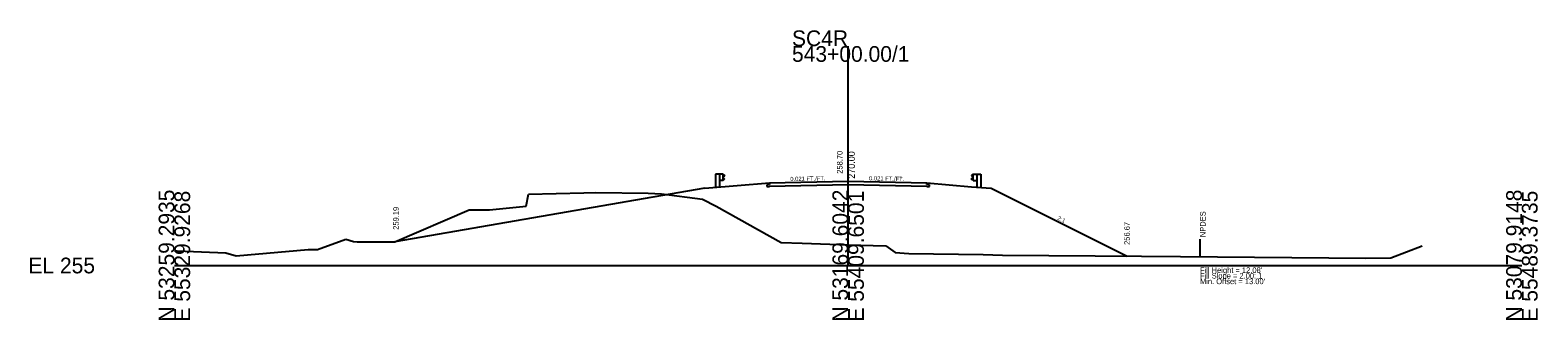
# Model space of a CAD drawing. Extents: x 9740 to 17409, y 8856 to 28416.
# Drawn here: x 11740.2 to 12008.7, y 23861.7 to 23913.3 of the extents above; entities that cross this region are included whole.
import ezdxf

# ---------------------------------------------------------------- set-up
doc = ezdxf.new("R2010")
doc.units = 0
for name, color, linetype in [('Level 10', 7, 'Continuous'), ('Level 11', 7, 'Continuous'), ('Level 12', 7, 'Continuous'), ('Level 24', 7, 'Continuous'), ('Level 32', 7, 'Continuous'), ('Level 33', 7, 'Continuous'), ('Level 50', 7, 'Continuous'), ('Level 55', 7, 'Continuous'), ('Level 59', 7, 'Continuous'), ('Level 6', 7, 'Continuous'), ('Level 60', 7, 'Continuous'), ('Level 63', 7, 'Continuous'), ('Level 7', 7, 'Continuous')]:
    doc.layers.add(name, color=color, linetype=linetype)

msp = doc.modelspace()

# ---------------------------------------------------------------- linework, layer by layer
at = {"layer": 'Level 11'}
for p, q in [((11871.85, 23885.79), (11871.35, 23885.78)), ((11871.35, 23885.78), (11871.35, 23885.44)), ((11871.35, 23885.44), (11871.85, 23885.45)), ((11871.85, 23886.09), (11871.85, 23885.79)), ((11899.85, 23885.79), (11899.85, 23886.09)), ((11900.35, 23885.78), (11899.85, 23885.79)), ((11899.85, 23885.45), (11900.35, 23885.44)), ((11900.35, 23885.44), (11900.35, 23885.78))]:
    msp.add_line(p, q, dxfattribs=at)
at = {"layer": 'Level 12'}
for p, q in [((11885.85, 23885.74), (11871.85, 23885.45)), ((11899.85, 23885.45), (11885.85, 23885.74))]:
    msp.add_line(p, q, dxfattribs=at)
at = {"layer": 'Level 24'}
for p, q in [((11862.92, 23887.67), (11862.25, 23887.67)), ((11862.25, 23887.67), (11862.25, 23885.29)), ((11863.58, 23887.67), (11862.92, 23887.67)), ((11862.92, 23887.67), (11862.92, 23885.34)), ((11863.58, 23886.51), (11862.92, 23886.51)), ((11863.58, 23886.51), (11863.58, 23887.67)), ((11863.58, 23887.6), (11863.85, 23887.4)), ((11863.85, 23887.35), (11863.58, 23887.15)), ((11863.85, 23886.83), (11863.58, 23887.03)), ((11863.58, 23886.58), (11863.85, 23886.78)), ((11863.85, 23887.4), (11863.85, 23887.35)), ((11863.85, 23886.78), (11863.85, 23886.83)), ((11908.12, 23887.6), (11907.85, 23887.4)), ((11907.85, 23887.4), (11907.85, 23887.35)), ((11907.85, 23887.35), (11908.12, 23887.15)), ((11907.85, 23886.83), (11908.12, 23887.03)), ((11907.85, 23886.78), (11907.85, 23886.83)), ((11908.12, 23886.58), (11907.85, 23886.78)), ((11908.12, 23886.51), (11908.12, 23887.67)), ((11908.12, 23887.67), (11908.79, 23887.67)), ((11908.12, 23886.51), (11908.79, 23886.51)), ((11908.79, 23887.67), (11908.79, 23885.34)), ((11908.79, 23887.67), (11909.46, 23887.67)), ((11909.46, 23887.67), (11909.46, 23885.29))]:
    msp.add_line(p, q, dxfattribs=at)
at = {"layer": 'Level 55'}
msp.add_line((11948.52, 23873.05), (11948.52, 23876.05), dxfattribs=at)
at = {"layer": 'Level 59'}
for p, q in [((11871.85, 23886.09), (11885.85, 23886.38)), ((11885.85, 23886.38), (11899.85, 23886.09))]:
    msp.add_line(p, q, dxfattribs=at)
at = {"layer": 'Level 6'}
for p, q in [((11860.35, 23885.13), (11871.85, 23886.09)), ((11899.85, 23886.09), (11907.85, 23885.42)), ((11907.85, 23885.42), (11911.35, 23885.13))]:
    msp.add_line(p, q, dxfattribs=at)
at = {"layer": 'Level 60'}
for p, q in [((11828.5, 23881.95), (11828.94, 23884.11)), ((11828.94, 23884.11), (11838.77, 23884.35)), ((11838.77, 23884.35), (11840.89, 23884.41)), ((11840.89, 23884.41), (11850.24, 23884.25)), ((11850.24, 23884.25), (11852.62, 23884.17)), ((11852.62, 23884.17), (11859.9, 23883.19)), ((11805.14, 23875.57), (11818.34, 23881.3)), ((11818.34, 23881.3), (11821.98, 23881.3)), ((11821.98, 23881.3), (11828.5, 23881.95)), ((11859.9, 23883.19), (11862.33, 23881.93)), ((11862.33, 23881.93), (11873.9, 23875.48)), ((11791.32, 23874.2), (11796.4, 23876.07)), ((11796.4, 23876.07), (11797.77, 23875.63)), ((11797.77, 23875.63), (11798.38, 23875.6)), ((11798.38, 23875.6), (11805.14, 23875.57)), ((11873.9, 23875.48), (11877.69, 23875.35)), ((11765.85, 23874.02), (11766.34, 23874.02)), ((11766.34, 23874.02), (11775, 23873.65)), ((11775, 23873.65), (11776.87, 23873.1)), ((11776.87, 23873.1), (11789.7, 23874.24)), ((11789.7, 23874.24), (11791.32, 23874.2)), ((11877.69, 23875.35), (11885.85, 23875.08)), ((11885.85, 23875.08), (11892.59, 23874.86)), ((11892.59, 23874.86), (11894.24, 23873.71)), ((11894.24, 23873.71), (11896.67, 23873.49)), ((11896.67, 23873.49), (11909.88, 23873.33)), ((11909.88, 23873.33), (11913.35, 23873.19)), ((11913.35, 23873.19), (11938.08, 23873.03)), ((11938.08, 23873.03), (11945.04, 23872.99)), ((11945.04, 23872.99), (11978.07, 23872.67)), ((11978.07, 23872.67), (11982.49, 23872.73)), ((11982.49, 23872.73), (11988.08, 23874.88))]:
    msp.add_line(p, q, dxfattribs=at)
at = {"layer": 'Level 63'}
for p, q in [((11885.85, 23871.38), (11885.85, 23910.48)), ((11765.85, 23871.38), (11885.85, 23871.38)), ((11885.85, 23871.38), (12005.85, 23871.38))]:
    msp.add_line(p, q, dxfattribs=at)
at = {"layer": 'Level 7'}
for p, q in [((11860.35, 23885.13), (11805.14, 23875.57)), ((11911.35, 23885.13), (11935.52, 23873.05))]:
    msp.add_line(p, q, dxfattribs=at)

# ---------------------------------------------------------------- texts
at = {"layer": 'Level 10'}
msp.add_text('258.70', height=1, rotation=90, dxfattribs=at).set_placement((11884.85, 23887.73))
at = {"layer": 'Level 32'}
for s, rotation, p in [('0.021 FT./FT.', 1.1916, (11875.56, 23886.42)), ('0.021 FT./FT.', 358.8084, (11889.57, 23886.55)), ('2:1', 333.435, (11923.04, 23879.57))]:
    msp.add_text(s, height=0.75, rotation=rotation, dxfattribs=at).set_placement(p)
at = {"layer": 'Level 33'}
for s, p in [('259.19', (11805.81, 23877.74)), ('256.67', (11936.02, 23875.05))]:
    msp.add_text(s, height=1, rotation=90, dxfattribs=at).set_placement(p)
at = {"layer": 'Level 50'}
msp.add_text(' NPDES', height=1, rotation=90, dxfattribs=at).set_placement((11949.52, 23876.05))
for s, p in [("Fill Height = 12.08' ", (11948.52, 23870.05)), ('Fill Slope = 2.00: 1', (11948.52, 23869.05)), ("Min. Offset = 13.00' ", (11948.52, 23868.05))]:
    msp.add_text(s, height=1, dxfattribs=at).set_placement(p)
at = {"layer": 'Level 59'}
msp.add_text(' 270.00', height=1.2, rotation=90, dxfattribs=at).set_placement((11887.05, 23886.38))
at = {"layer": 'Level 63'}
for s, p in [('SC4R', (11875.85, 23910.48)), ('543+00.00/1', (11875.85, 23907.68)), ('EL 255', (11739.85, 23869.98))]:
    msp.add_text(s, height=2.8, dxfattribs=at).set_placement(p)
for s, p in [('N 53259.2935', (11765.85, 23861.38)), ('E 55329.9268', (11768.65, 23861.38)), ('N 53169.6042', (11885.85, 23861.38)), ('E 55409.6501', (11888.65, 23861.38)), ('N 53079.9148', (12005.85, 23861.38)), ('E 55489.3735', (12008.65, 23861.38))]:
    msp.add_text(s, height=2.8, rotation=90, dxfattribs=at).set_placement(p)

doc.saveas('drawing.dxf')
